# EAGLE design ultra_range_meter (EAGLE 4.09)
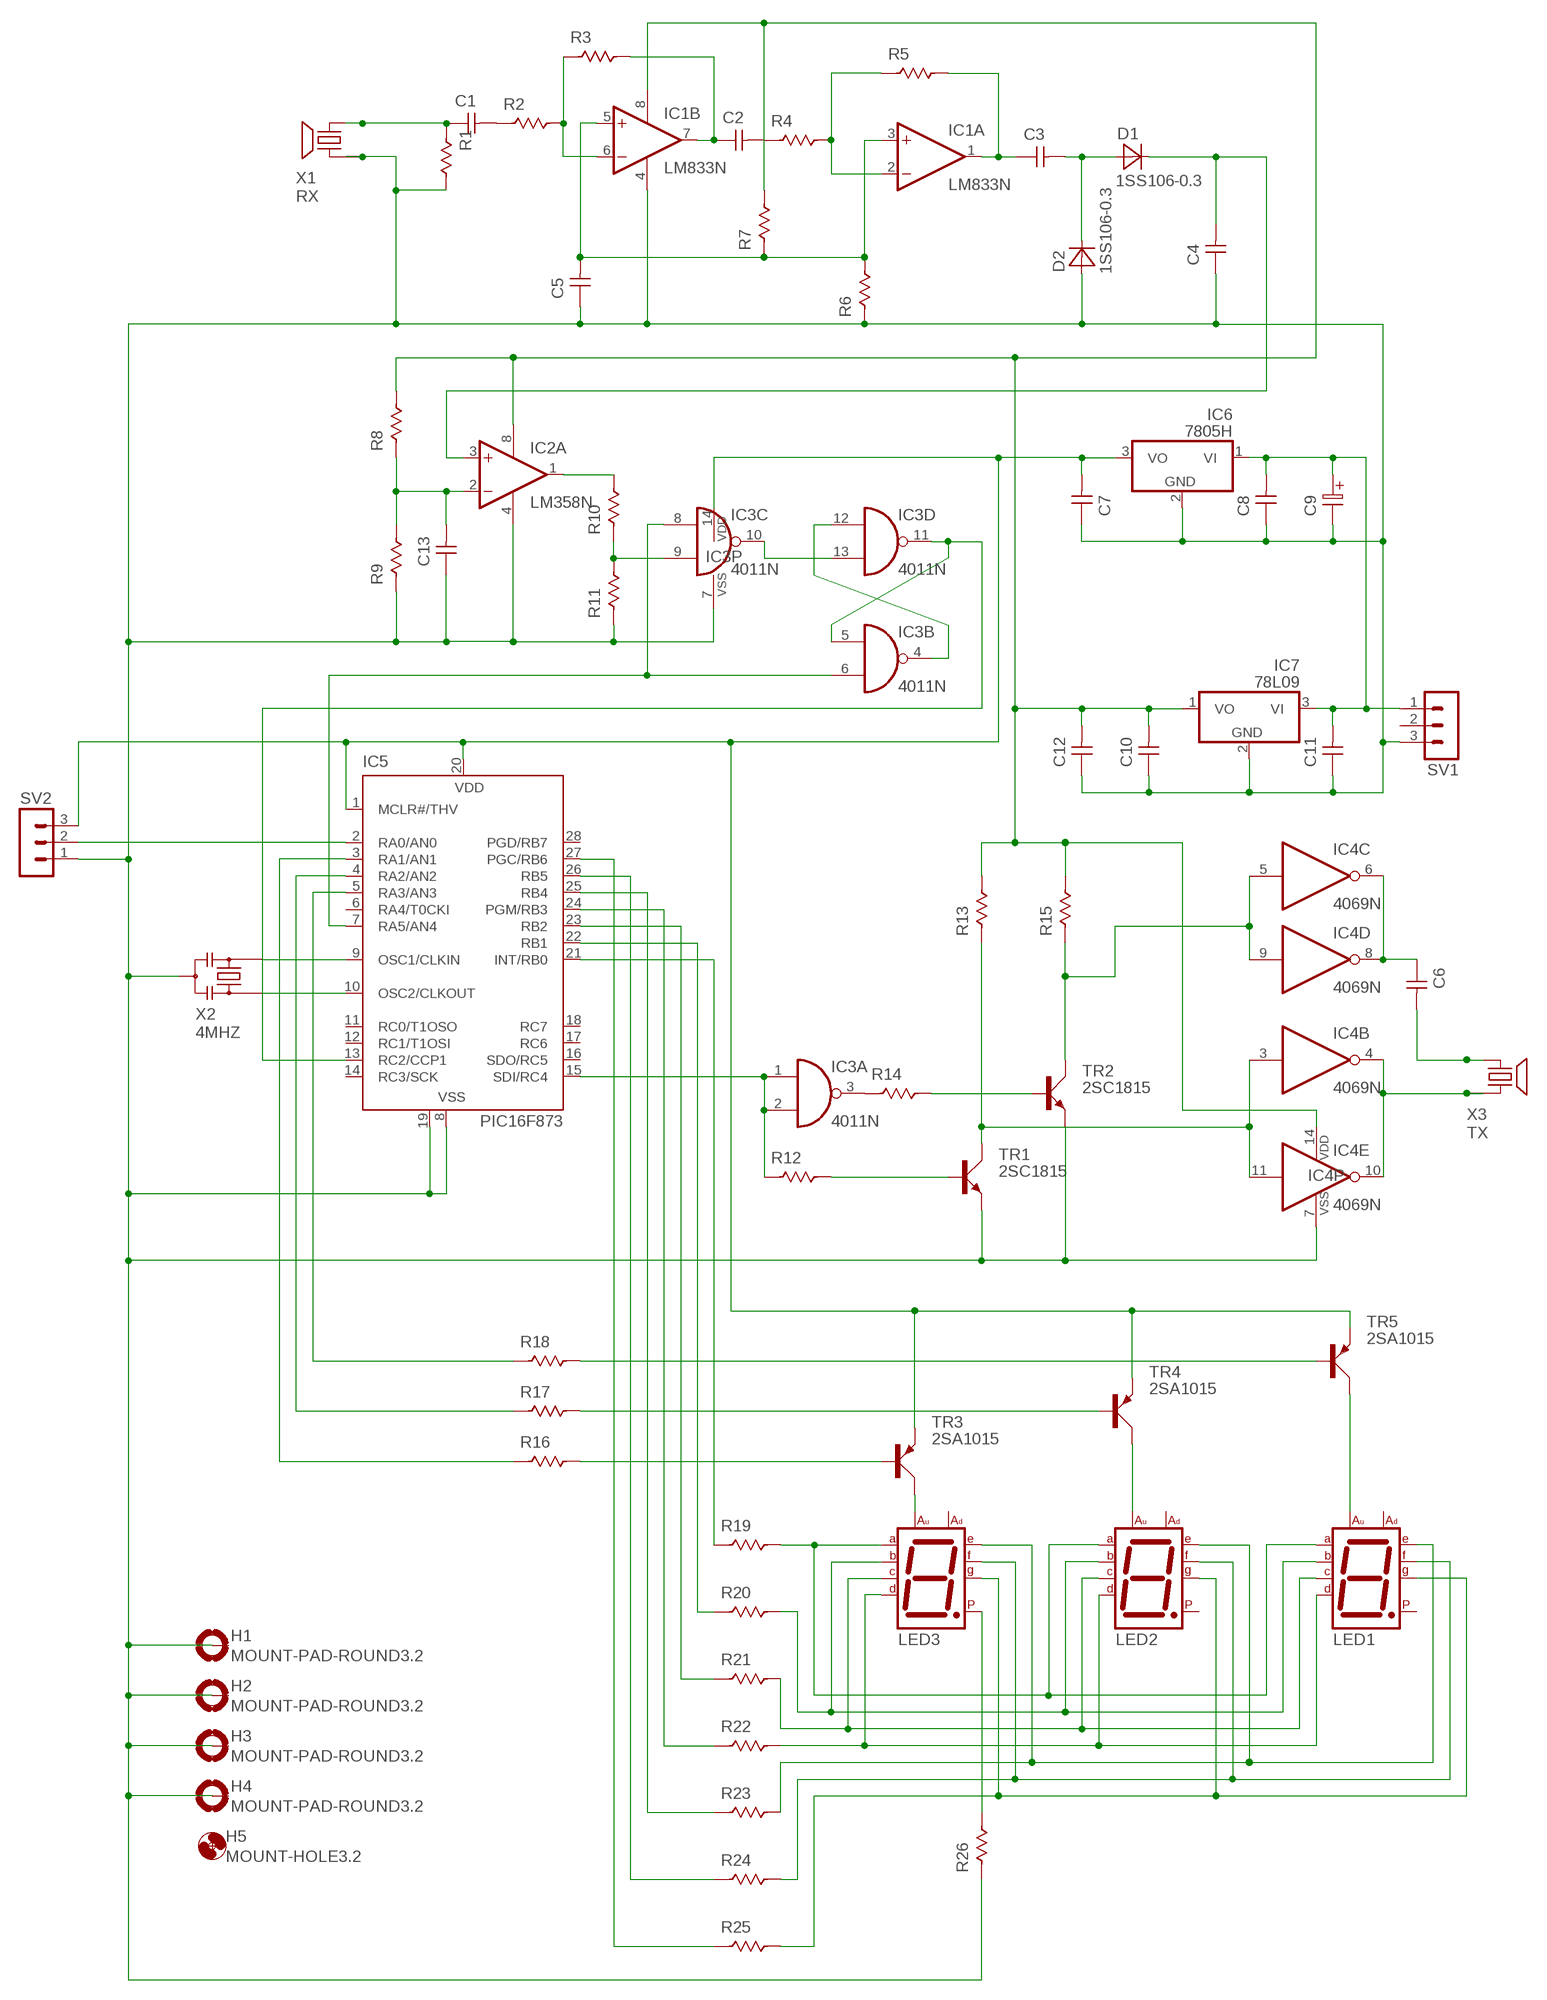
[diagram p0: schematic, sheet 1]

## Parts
C1  CAP-0.1  [C-0.1]
C2  CAP-0.1  [C-0.1]
C3  CAP-0.1  [C-0.1]
C4  CAP-0.1  [C-0.1]
C5  CAP-0.1  [C-0.1]
C6  CAP-0.1  [C-0.1]
C7  CAP-0.1  [C-0.1]
C8  CAP-0.1  [C-0.1]
C9  ELC-0.1X0.2  [E-0.1X0.2]
C10  CAP-0.1  [C-0.1]
C11  CAP-0.1  [C-0.1]
C12  CAP-0.1  [C-0.1]
C13  CAP-0.1  [C-0.1]
D1  1SS106-0.3  [D-0.3]
D2  1SS106-0.3  [D-0.3]
H1  MOUNT-PAD-ROUND3.2  [3,2-PAD]
H2  MOUNT-PAD-ROUND3.2  [3,2-PAD]
H3  MOUNT-PAD-ROUND3.2  [3,2-PAD]
H4  MOUNT-PAD-ROUND3.2  [3,2-PAD]
H5  MOUNT-HOLE3.2  [3,2]
IC1  LM833N  [DIL08]
IC2  LM358N  [DIL08]
IC3  4011N  [DIL14]
IC4  4069N  [DIL14]
IC5  PIC16F873  [DIL28-3]
IC6  7805H  [TO220H]
IC7  78L09  78L05  [TO92]
LED1  7SEG-A  [7SEG-13]
LED2  7SEG-A  [7SEG-13]
LED3  7SEG-A  [7SEG-13]
R1  RESI-0.3  [R-0.3]
R2  RESI-0.1  [R-0.1]
R3  RESI-0.1  [R-0.1]
R4  RESI-0.3  [R-0.3]
R5  RESI-0.1  [R-0.1]
R6  RESI-0.1  [R-0.1]
R7  RESI-0.1  [R-0.1]
R8  RESI-0.3  [R-0.3]
R9  RESI-0.3  [R-0.3]
R10  RESI-0.3  [R-0.3]
R11  RESI-0.3  [R-0.3]
R12  RESI-0.3  [R-0.3]
R13  RESI-0.3  [R-0.3]
R14  RESI-0.3  [R-0.3]
R15  RESI-0.3  [R-0.3]
R16  RESI-0.1  [R-0.1]
R17  RESI-0.1  [R-0.1]
R18  RESI-0.1  [R-0.1]
R19  RESI-0.3  [R-0.3]
R20  RESI-0.3  [R-0.3]
R21  RESI-0.3  [R-0.3]
R22  RESI-0.3  [R-0.3]
R23  RESI-0.3  [R-0.3]
R24  RESI-0.3  [R-0.3]
R25  RESI-0.3  [R-0.3]
R26  RESI-0.3  [R-0.3]
SV1  MA03-1  [MA03-1]
SV2  MA03-1  [MA03-1]
TR1  2SC1815  [TO92BCE]
TR2  2SC1815  [TO92BCE]
TR3  2SA1015  [TO92BCE]
TR4  2SA1015  [TO92BCE]
TR5  2SA1015  [TO92BCE]
X1  RX  [RX]
X2  4MHZ  [RESONATOR]
X3  TX  [TX]

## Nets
N$1: C1.1 R1.2 X1.1 X1.2
N$2: C1.2 R2.2
N$3: C2.2 R4.2
N$4: IC5.10(OSC2/CLKOUT) X2.3
N$5: IC5.9(OSC1/CLKIN) X2.1
N$6: IC5.21(INT/RB0) R19.2
N$7: IC5.22(RB1) R20.2
N$8: IC5.23(RB2) R21.2
N$9: IC5.24(PGM/RB3) R22.2
N$10: IC5.25(RB4) R23.2
N$11: IC5.26(RB5) R24.2
N$12: IC5.27(PGC/RB6) R25.2
N$13: IC3.1(A:I0) IC3.2(A:I1) IC5.15(SDI/RC4) R12.2
N$14: IC3.3(A:O) R14.2
N$15: IC5.2(RA0/AN0) SV2.2
N$16: IC5.5(RA3/AN3) R18.2
N$17: IC5.4(RA2/AN2) R17.2
N$18: IC5.3(RA1/AN1) R16.2
N$19: R16.1 TR3.B
N$20: R17.1 TR4.B
N$21: R18.1 TR5.B
N$22: R12.1 TR1.B
N$23: R14.1 TR2.B
N$24: LED1.4(C) LED2.4(C) LED3.4(C) R21.1
N$25: LED1.6(B) LED2.6(B) LED3.6(B) R20.1
N$26: IC4.3(B:I) IC4.11(E:I) R13.2 TR1.C
N$27 [power]: C8.2 C9.1 C11.2 IC6.1(VI) IC7.3(VI) SV1.1
N$28: C6.1 IC4.6(C:O) IC4.8(D:O)
N$29: LED1.1(E) LED2.1(E) LED3.1(E) R23.1
N$30: LED1.9(F) LED2.9(F) LED3.9(F) R24.1
N$31: C6.2 X3.1 X3.2
N$32: IC4.4(B:O) IC4.10(E:O) X3.3 X3.4
N$33: LED3.8(CA1) TR3.C
N$34: LED2.8(CA1) TR4.C
N$35: LED1.8(CA1) TR5.C
N$36: LED1.10(G) LED2.10(G) LED3.10(G) R25.1
N$37: IC1.2(A:-IN) R4.1 R5.2
N$38: C3.1 IC1.1(A:OUT) R5.1
N$39: C3.2 D1.A D2.K
N$40: C13.2 IC2.2(A:-IN) R8.2 R9.1
N$41 [power]: C7.2 IC3.14(P:VDD) IC5.1(MCLR#/THV) IC5.20(VDD) IC6.3(VO) SV2.3 TR3.E TR4.E TR5.E
N$42: IC2.1(A:OUT) R10.1
N$43: LED3.5(DP) R26.1
N$44: LED1.2(D) LED2.2(D) LED3.2(D) R22.1
N$45: IC3.9(C:I1) R10.2 R11.1
N$46: C4.2 D1.K IC2.3(A:+IN)
N$47: LED1.7(A) LED2.7(A) LED3.7(A) R19.1
N$48: IC3.5(B:I0) IC3.11(D:O) IC5.13(RC2/CCP1)
N$49: IC4.5(C:I) IC4.9(D:I) R15.2 TR2.C
N$50: IC3.4(B:O) IC3.12(D:I0)
N$51: IC3.10(C:O) IC3.13(D:I1)
N$52 [gnd]: C4.1 C5.1 C7.1 C8.1 C9.2 C10.1 C11.1 C12.1 C13.1 D2.A H1.B3,2(MOUNT) H2.B3,2(MOUNT) H3.B3,2(MOUNT) H4.B3,2(MOUNT) IC1.4(P:V-) IC2.4(P:V-) IC3.7(P:VSS) IC4.7(P:VSS) IC5.8(VSS) IC5.19(VSS) IC6.2(GND) IC7.2(GND) R1.1 R6.2 R9.2 R11.2 R26.2 SV1.3 SV2.1 TR1.E TR2.E X1.3 X1.4 X2.2
N$53: IC1.6(B:-IN) R2.1 R3.2
N$55: C2.1 IC1.7(B:OUT) R3.1
N$56: IC3.6(B:I1) IC3.8(C:I0) IC5.7(RA5/AN4)
N$57: C5.2 IC1.3(A:+IN) IC1.5(B:+IN) R6.1 R7.2
N$60 [power]: C10.2 C12.2 IC1.8(P:V+) IC2.8(P:V+) IC4.14(P:VDD) IC7.1(VO) R7.1 R8.1 R13.1 R15.1
Unconnected: IC2.5(B:+IN) IC2.6(B:-IN) IC2.7(B:OUT) IC4.1(A:I) IC4.2(A:O) IC4.12(F:O) IC4.13(F:I) IC5.6(RA4/T0CKI) IC5.11(RC0/T1OSO) IC5.12(RC1/T1OSI) IC5.14(RC3/SCK) IC5.16(SDO/RC5) IC5.17(RC6) IC5.18(RC7) IC5.28(PGD/RB7) LED1.3(CA2) LED1.5(DP) LED2.3(CA2) LED2.5(DP) LED3.3(CA2) SV1.2

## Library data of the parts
C1-C8 C10-C13 = 01_Capacitor:CAP-*: Non Pole Capacitor
C9 = 01_Capacitor:ELC-*: Electrolytic Capacitor
D1 D2 = 03_Diode:1SS106: Shottky barrier diode
H1-H4 = 92_Holes:MOUNT-PAD-ROUND: MOUNTING PAD, round
H5 = 92_Holes:MOUNT-HOLE: MOUNTING HOLE with drill center marker
IC1 = 10_Linear:LM833: OP AMP
IC2 = 10_Linear:LM358: OP AMP
IC3 = 07_40xx:4011: Quad 2-input NAND
IC4 = 07_40xx:4069: Hex INVERTER
IC5 = 11_PIC:PIC16F873: MICROCONTROLLER flash type
IC6 IC7 = 12_Regulator:78*: Positive Voltage Regulator
LED1-LED3 = 13_LED:7SEG-A: 7-segment LED Anode Common
R1-R26 = 02_Resistor:RESI-*: Resistor
SV1 SV2 = 91_Connector:MA03-1: PIN HEADER
TR1 TR2 = 05_Transistors:2SC*: NPN Transistor
TR3-TR5 = 05_Transistors:2SA*: PNP Transistor
X1 = 15_Sonar:RX: Receive Sonar
X2 = 14_Crystal:*MHZ: Resonator
X3 = 15_Sonar:TX: Transmit Sonar

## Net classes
1 gnd: width 0.914 mm, drill 0.254 mm
2 power: width 0.61 mm, drill 0.203 mm

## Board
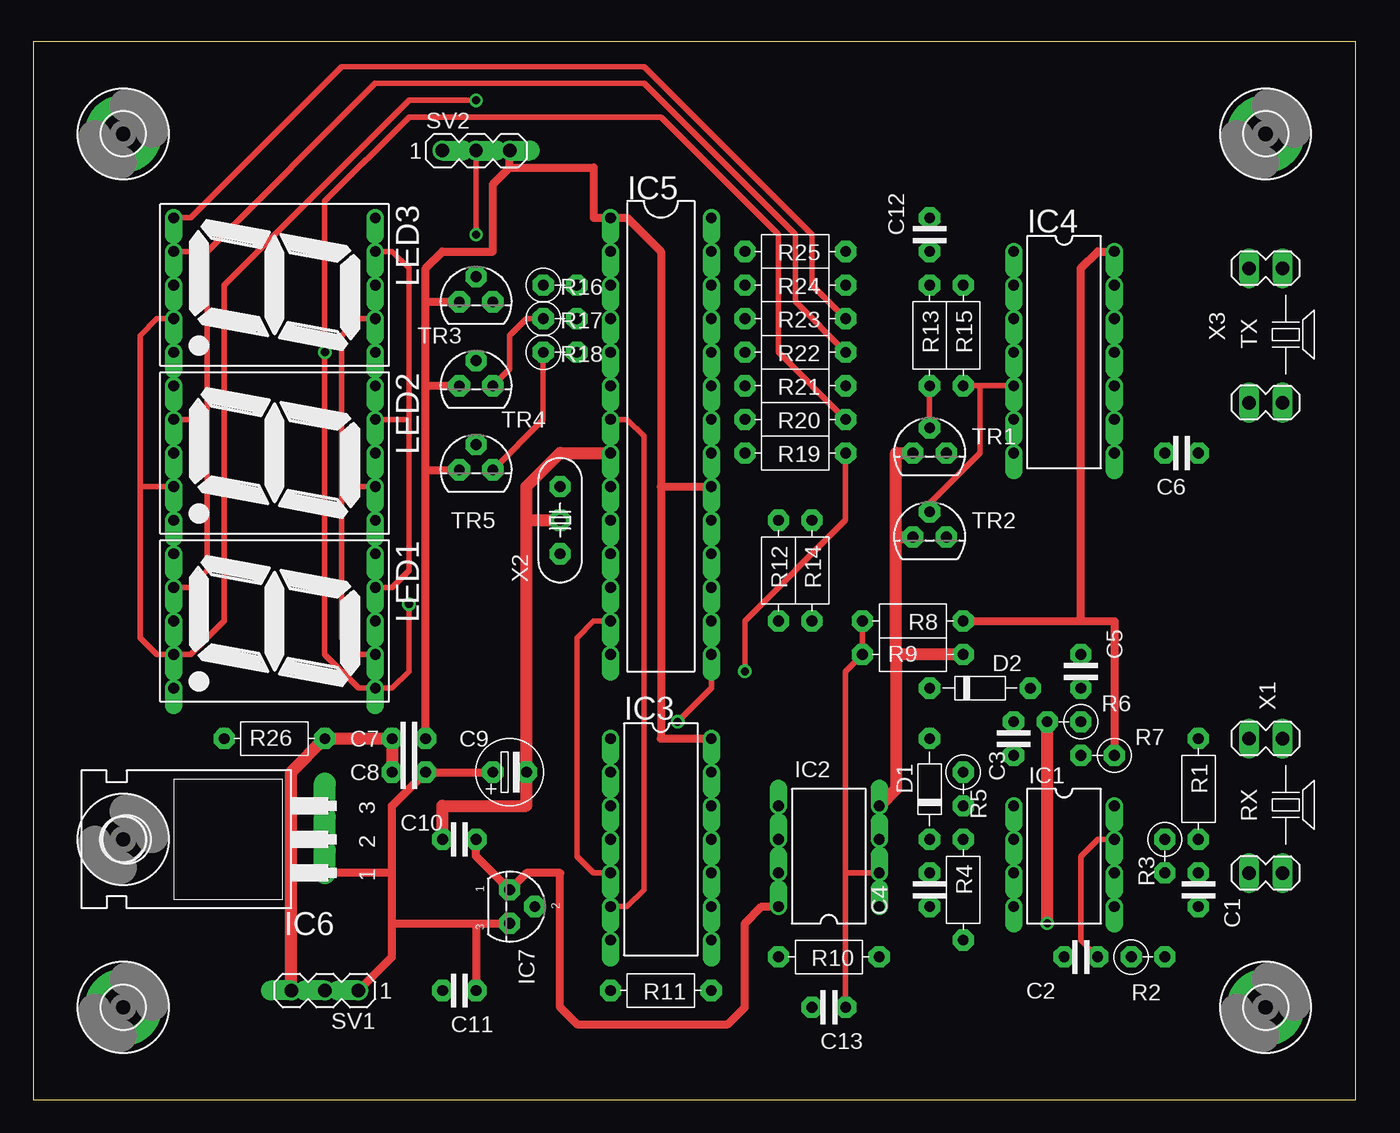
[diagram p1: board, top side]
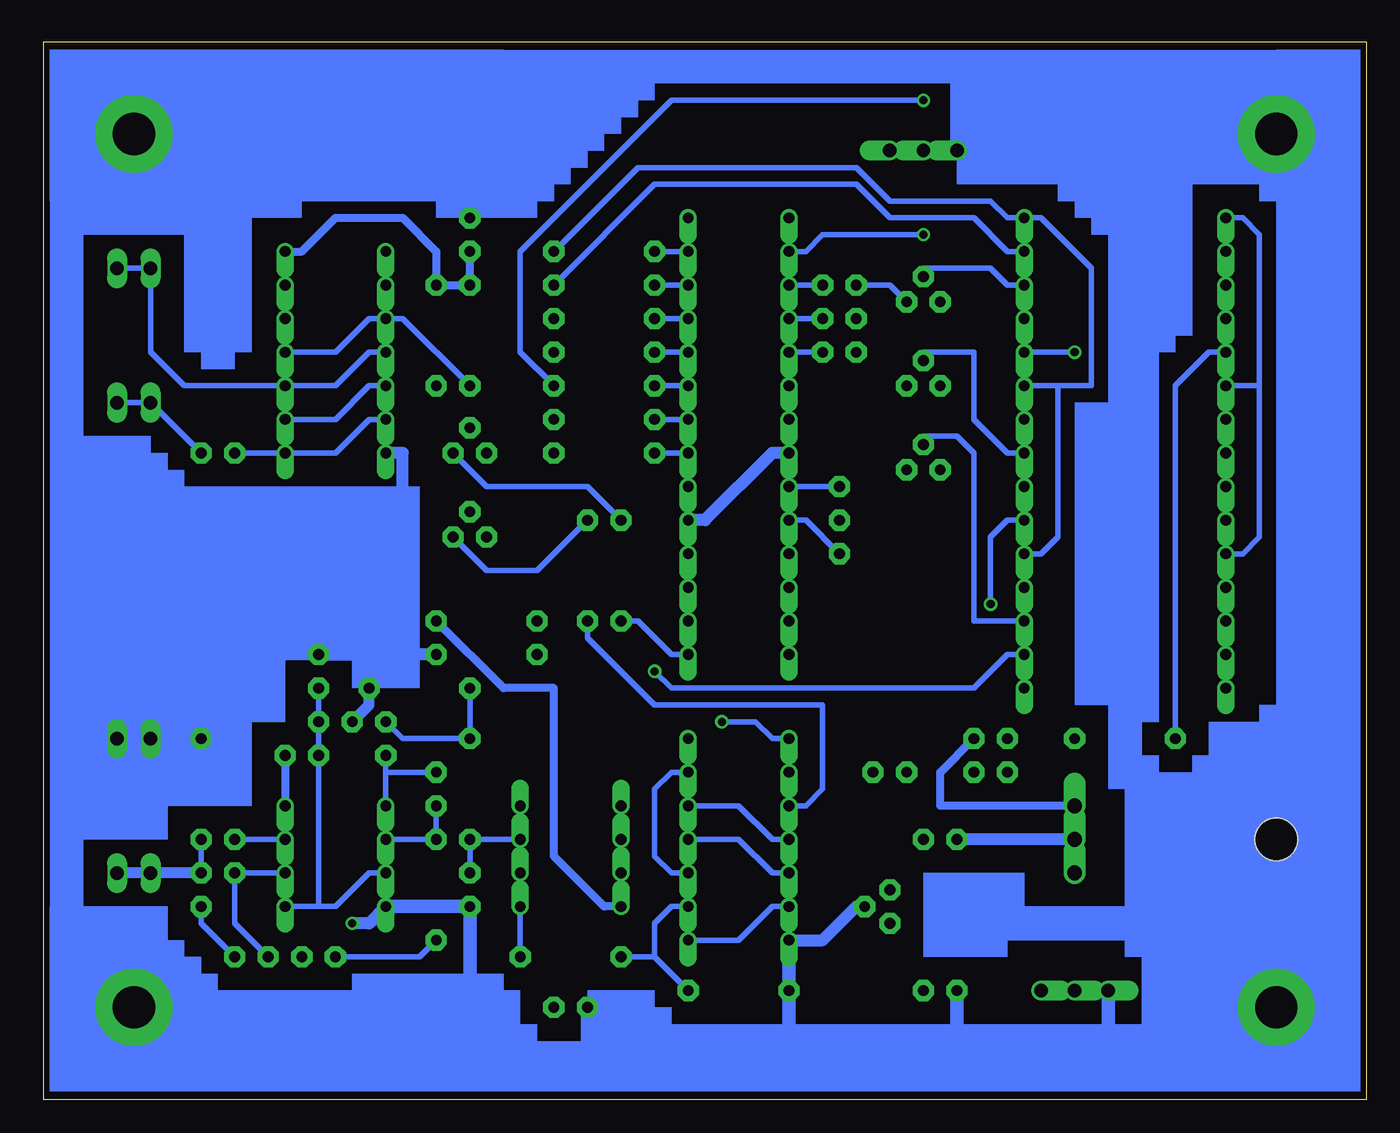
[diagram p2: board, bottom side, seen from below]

Size 100 x 80 mm. Coordinates in mm from the lower left corner, seen from the top.
Outline: 0,0 100,0 100,80 0,80 0,0
Copper layers used: Top, Bottom

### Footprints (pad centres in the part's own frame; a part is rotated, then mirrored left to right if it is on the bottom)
C-0.1 = drill 0.813 pad 1.6 octagon: 1 -1.27,0; 2 1.27,0
E-0.1X0.2 = drill 0.813 pad 1.6 octagon: 1 -1.27,0; 2 1.27,0
D-0.3 = drill 0.813 pad 1.6 octagon: A -3.81,0; K 3.81,0
3,2-PAD = drill 3.2 pad 5.842 round: B3,2 0,0
3,2 = hole 3.2: 0,0
DIL08 = drill 0.813 offset: 1 -3.81,-3.81; 2 -1.27,-3.81; 3 1.27,-3.81; 4 3.81,-3.81; 5 3.81,3.81; 6 1.27,3.81; 7 -1.27,3.81; 8 -3.81,3.81
DIL14 = drill 0.813 offset: 1 -7.62,-3.81; 2 -5.08,-3.81; 3 -2.54,-3.81; 4 0,-3.81; 5 2.54,-3.81; 6 5.08,-3.81; 7 7.62,-3.81; 8 7.62,3.81; 9 5.08,3.81; 10 2.54,3.81; 11 0,3.81; 12 -2.54,3.81; 13 -5.08,3.81; 14 -7.62,3.81
DIL28-3 = drill 0.813 offset: 1 -16.51,-3.81; 2 -13.97,-3.81; 3 -11.43,-3.81; 4 -8.89,-3.81; 5 -6.35,-3.81; 6 -3.81,-3.81; 7 -1.27,-3.81; 8 1.27,-3.81; 9 3.81,-3.81; 10 6.35,-3.81; 11 8.89,-3.81; 12 11.43,-3.81; 13 13.97,-3.81; 14 16.51,-3.81; 15 16.51,3.81; 16 13.97,3.81; 17 11.43,3.81; 18 8.89,3.81; 19 6.35,3.81; 20 3.81,3.81; 21 1.27,3.81; 22 -1.27,3.81; 23 -3.81,3.81; 24 -6.35,3.81; 25 -8.89,3.81; 26 -11.43,3.81; 27 -13.97,3.81; 28 -16.51,3.81
TO220H = drill 1.118 offset: 1 -2.54,-7.62; 2 0,-7.62; 3 2.54,-7.62
TO92 = drill 0.813 pad 1.6 octagon: 1 -1.27,0; 2 0,1.905; 3 1.27,0
7SEG-13 = drill 0.813 offset: 1 -5.08,-7.62; 2 -2.54,-7.62; 3 0,-7.62; 4 2.54,-7.62; 5 5.08,-7.62; 6 5.08,7.62; 7 2.54,7.62; 8 0,7.62; 9 -2.54,7.62; 10 -5.08,7.62
R-0.3 = drill 0.813 pad 1.6 octagon: 1 -3.81,0; 2 3.81,0
R-0.1 = drill 0.813 pad 1.6 octagon: 1 0,0; 2 2.54,0
MA03-1 = drill 1.016 offset: 1 -2.54,0; 2 0,0; 3 2.54,0
TO92BCE = drill 0.813 pad 1.6 octagon: B 1.27,-1.27; C 0,0.635; E -1.27,-1.27
RX = drill 1.016 long: 1 5.08,1.27; 2 5.08,-1.27; 3 -5.08,1.27; 4 -5.08,-1.27
RESONATOR = drill 0.813 pad 1.6 octagon: 1 -2.54,0; 2 0,0; 3 2.54,0
TX = drill 1.016 long: 1 5.08,1.27; 2 5.08,-1.27; 3 -5.08,1.27; 4 -5.08,-1.27

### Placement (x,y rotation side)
C1  88.1,15.87 270 top
C2  79.21,10.79 180 top
C3  74.13,27.3 90 top
C4  67.78,15.87 90 top
C5  79.21,32.38 270 top
C6  86.83,48.89 0 top
C7  28.41,27.3 0 top
C8  28.41,24.76 0 top
C9  36.03,24.76 0 top
C10  32.22,19.68 0 top
C11  32.22,8.25 0 top
C12  67.78,65.4 270 top
C13  60.16,6.98 0 top
D1  67.78,23.49 270 top
D2  71.59,31.11 180 top
H1  6.82,73.02 0 top
H2  6.82,6.98 0 top
H3  93.18,6.98 0 top
H4  93.18,73.02 0 top
H5  6.82,19.68 0 top
IC1  77.94,18.41 270 top
IC2  60.16,18.41 90 top
IC3  47.46,19.68 270 top
IC4  77.94,56.51 270 top
IC5  47.46,50.16 270 top
IC6  14.44,19.68 90 top
IC7  36.03,14.6 270 top
LED1  18.25,36.19 270 top
LED2  18.25,48.89 270 top
LED3  18.25,61.59 270 top
R1  88.1,23.49 270 top
R2  83.02,10.79 0 top
R3  85.56,19.68 270 top
R4  70.32,15.87 270 top
R5  70.32,24.76 270 top
R6  79.21,28.57 180 top
R7  81.75,26.03 180 top
R8  66.51,36.19 180 top
R9  66.51,33.65 0 top
R10  60.16,10.79 180 top
R11  47.46,8.25 180 top
R12  56.35,40 270 top
R13  67.78,57.78 270 top
R14  58.89,40 270 top
R15  70.32,57.78 270 top
R16  38.57,61.59 0 top
R17  38.57,59.05 0 top
R18  38.57,56.51 0 top
R19  57.62,48.89 180 top
R20  57.62,51.43 180 top
R21  57.62,53.97 180 top
R22  57.62,56.51 180 top
R23  57.62,59.05 180 top
R24  57.62,61.59 180 top
R25  57.62,64.13 180 top
R26  18.25,27.3 0 top
SV1  22.06,8.25 180 top
SV2  33.49,71.75 0 top
TR1  67.78,50.16 0 top
TR2  67.78,43.81 0 top
TR3  33.49,61.59 0 top
TR4  33.49,55.24 0 top
TR5  33.49,48.89 0 top
X1  93.18,22.22 270 top
X2  39.84,43.81 270 top
X3  93.18,57.78 270 top

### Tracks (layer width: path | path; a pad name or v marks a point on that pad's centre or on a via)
N$1
  Bottom 0.406: C1.1 R1.2
  Bottom 0.813: C1.1 X1.2 X1.1
N$2
  Bottom 0.406: R2.2 88.1,13.33 C1.2
N$3
  Bottom 0.406: R4.2 71.59,10.79 C2.2
N$4
  Bottom 0.406: X2.3 42.38,43.81 IC5.10
N$5
  Bottom 0.406: X2.1 IC5.9
N$6
  Bottom 0.406: IC5.21 R19.2
N$7
  Bottom 0.406: IC5.22 R20.2
N$8
  Bottom 0.406: IC5.23 R21.2
N$9
  Bottom 0.406: IC5.24 R22.2
N$10
  Bottom 0.406: IC5.25 R23.2
N$11
  Bottom 0.406: IC5.26 R24.2
N$12
  Bottom 0.406: IC5.27 R25.2
N$13  (via drill 0.61)
  Top 0.406: v48.73,28.57 51.27,31.11 IC5.15
  Bottom 0.406: R12.2 55.08,36.19 52.54,33.65 IC5.15 | v48.73,28.57 46.19,28.57 44.92,27.3 IC3.1 IC3.2
N$14
  Bottom 0.406: R14.2 58.89,34.92 53.81,29.84 41.11,29.84 41.11,23.49 42.38,22.22 IC3.3
N$15  (via drill 0.61)
  Top 0.406: v33.49,65.4 SV2.2
  Bottom 0.406: v33.49,65.4 41.11,65.4 42.38,64.13 IC5.2
N$16
  Bottom 0.406: R18.2 IC5.5
N$17
  Bottom 0.406: R17.2 IC5.4
N$18
  Bottom 0.406: R16.2 IC5.3
N$19
  Bottom 0.406: TR3.B 36.03,61.59 R16.1
N$20
  Top 0.406: TR4.B 36.03,55.24 36.03,57.78 37.3,59.05 R17.1
N$21
  Top 0.406: TR5.B 38.57,51.43 R18.1
N$22
  Bottom 0.406: R12.1 58.89,46.35 66.51,46.35 TR1.B
N$23
  Bottom 0.406: R14.1 62.7,40 66.51,40 TR2.B
N$24  (via drill 0.61)
  Top 0.406: 8.09,46.35 8.09,34.92 9.36,33.65 LED1.4 11.9,33.65 14.44,36.19 14.44,61.59 28.41,75.56 v33.49,75.56 | 8.09,46.35 LED2.4 | 8.09,46.35 8.09,57.78 9.36,59.05 LED3.4
  Bottom 0.406: R21.1 63.97,56.51 63.97,64.13 52.54,75.56 v33.49,75.56
N$25  (via drill 0.61)
  Top 0.406: v28.41,37.46 28.41,32.38 27.14,31.11 LED1.6 24.6,31.11 22.06,33.65 v22.06,56.51 22.06,67.94 28.41,74.29 47.46,74.29 56.35,65.4 56.35,56.51 R20.1
  Bottom 0.406: v28.41,37.46 28.41,42.54 27.14,43.81 LED2.6 | v22.06,56.51 LED3.6
N$26
  Top 0.406: TR1.C R13.2
  Bottom 0.406: R13.2 72.86,59.05 IC4.3 75.4,59.05 77.94,56.51 IC4.11
N$27
  Top 0.61: 33.49,13.33 IC7.3 | C9.1 C8.2 27.14,22.22 27.14,13.33 | 27.14,13.33 27.14,17.14 IC6.1 | SV1.1 27.14,10.79 27.14,13.33 | 27.14,13.33 33.49,13.33 | 33.49,13.33 C11.2
N$28
  Bottom 0.406: IC4.6 75.4,51.43 77.94,48.89 IC4.8 C6.1
N$29
  Top 0.406: R23.1 58.89,61.59 58.89,65.4 46.19,78.1 23.33,78.1 11.9,66.67 LED3.1
  Bottom 0.406: 8.09,53.97 8.09,42.54 9.36,41.27 LED1.1 | 8.09,53.97 LED2.1 | 8.09,53.97 8.09,65.4 9.36,66.67 LED3.1
N$30
  Top 0.406: 28.41,51.43 28.41,40 27.14,38.73 LED1.9 | 28.41,51.43 LED2.9 | 28.41,51.43 28.41,62.86 27.14,64.13 LED3.9
  Bottom 0.406: R24.1 53.81,69.21 38.57,69.21 36.03,66.67 29.68,66.67 27.14,64.13 LED3.9
N$31
  Bottom 0.406: C6.2 X3.2 X3.1
N$32
  Bottom 0.406: IC4.4 75.4,56.51 77.94,53.97 IC4.10 89.37,53.97 91.91,56.51 X3.4 X3.3
N$33
  Bottom 0.406: LED3.8 27.14,61.59 28.41,62.86 33.49,62.86 TR3.C
N$34
  Bottom 0.406: LED2.8 27.14,48.89 29.68,51.43 29.68,56.51 33.49,56.51 TR4.C
N$35
  Bottom 0.406: LED1.8 29.68,36.19 29.68,48.89 30.95,50.16 33.49,50.16 TR5.C
N$36
  Bottom 0.406: 23.33,53.97 23.33,42.54 24.6,41.27 LED1.10 | 23.33,53.97 LED2.10 | 23.33,53.97 20.79,53.97 20.79,62.86 24.6,66.67 LED3.10 27.14,66.67 28.41,67.94 36.03,67.94 38.57,70.48 55.08,70.48 R25.1
N$37
  Bottom 0.406: IC1.2 R4.1 R5.2
N$38
  Bottom 0.406: 74.13,24.76 IC1.1 | 74.13,24.76 C3.1 | R5.1 74.13,24.76
N$39
  Bottom 0.406: C3.2 72.86,27.3 D1.A D2.K
N$40
  Top 0.406: R8.2 R9.1 61.43,32.38 61.43,17.14 | C13.2 61.43,17.14 | 61.43,17.14 IC2.2
N$41
  Top 0.61: 47.46,46.35 47.46,27.3 IC3.14 | 47.46,46.35 47.46,64.13 44.92,66.67 IC5.1 42.38,66.67 42.38,70.48 36.03,70.48 | 47.46,46.35 IC5.20 | 29.68,47.62 TR5.E | C7.2 29.68,47.62 | 29.68,53.97 TR4.E | 29.68,47.62 29.68,53.97 | 29.68,60.32 TR3.E | 29.68,53.97 29.68,60.32 | 36.03,70.48 34.76,69.21 34.76,64.13 30.95,64.13 29.68,62.86 29.68,60.32 | 36.03,70.48 SV2.3
  Bottom 0.61: C7.2 32.22,24.76 32.22,22.22 IC6.3
N$42
  Bottom 0.406: R10.1 IC2.1
N$43
  Bottom 0.406: R26.1 14.44,53.97 11.9,56.51 LED3.5
N$44
  Top 0.406: 13.17,51.43 13.17,40 11.9,38.73 LED1.2 | 13.17,51.43 LED2.2 | 13.17,51.43 13.17,64.13 | 13.17,64.13 LED3.2 | R22.1 57.62,60.32 57.62,65.4 46.19,76.83 25.87,76.83 13.17,64.13
N$45
  Bottom 0.406: R11.1 53.81,10.79 | 53.81,10.79 53.81,13.33 52.54,14.6 IC3.9 | 53.81,10.79 R10.2
N$46
  Bottom 0.406: C4.2 D1.K IC2.3
N$47  (via drill 0.61)
  Top 0.406: 23.33,46.35 23.33,34.92 24.6,33.65 LED1.7 | 23.33,46.35 LED2.7 | 23.33,46.35 23.33,57.78 24.6,59.05 LED3.7 | R19.1 61.43,43.81 53.81,36.19 v53.81,32.38
  Bottom 0.406: v53.81,32.38 52.54,31.11 29.68,31.11 27.14,33.65 LED1.7
N$48
  Top 0.406: IC5.13 42.38,36.19 41.11,34.92 41.11,18.41 42.38,17.14 IC3.5
  Bottom 0.406: IC3.5 44.92,17.14 47.46,19.68 IC3.11
N$49
  Top 0.406: 71.59,53.97 71.59,48.89 67.78,45.08 TR2.C | 71.59,53.97 R15.2 | 71.59,53.97 IC4.5
  Bottom 0.406: IC4.9 77.94,51.43 75.4,53.97 IC4.5
N$50
  Bottom 0.406: IC3.4 44.92,19.68 47.46,22.22 IC3.12
N$51
  Bottom 0.406: IC3.10 52.54,17.14 53.81,18.41 53.81,23.49 52.54,24.76 IC3.13
N$52  (via drill 0.61)
  Top 0.914: C8.1 C7.1 R26.2 19.52,24.76 19.52,19.68 | 37.3,43.81 C9.2 37.3,22.22 30.95,22.22 C10.1 | 19.52,19.68 IC6.2 | SV1.3 19.52,19.68 | 37.3,43.81 X2.2 | 37.3,43.81 37.3,46.35 39.84,48.89 IC5.8 | R9.2 65.24,33.65 | 65.24,42.54 TR2.E | 65.24,33.65 65.24,42.54 | 65.24,33.65 65.24,23.49 IC2.4 | TR1.E 65.24,48.89 65.24,42.54 | v76.67,13.33 R6.2
  Bottom 0.813: R6.2 75.4,29.84 D2.A | 75.4,33.65 R9.2 | C5.1 88.1,33.65 R1.1 X1.4 X1.3 98.26,27.3
  Bottom 0.914: IC5.8 44.92,48.89 50,43.81 IC5.19 | D2.A 75.4,33.65 C5.1 81.75,33.65 | R9.2 72.86,33.65 72.86,48.89 IC4.7 | IC7.2 38.57,14.6 41.11,12.06 IC3.7 | IC6.2 C10.1 | IC1.4 75.4,13.33 v76.67,13.33
  Bottom 1.016: 19.52,3.17 SV1.3 | IC3.7 R11.2 43.65,3.17 | 30.95,3.17 C11.1 | 58.89,3.17 C13.1 | 67.78,3.17 C4.1 IC1.4 | 30.95,78.1 SV2.1 | 67.78,78.1 C12.1
  Bottom 2.54: H2.B3,2 6.82,3.17 19.52,3.17 30.95,3.17 43.65,3.17 58.89,3.17 67.78,3.17 93.18,3.17 H3.B3,2 98.26,6.98 98.26,27.3 98.26,73.02 H4.B3,2 93.18,78.1 67.78,78.1 30.95,78.1 6.82,78.1 H1.B3,2 3.01,73.02 3.01,6.98 H2.B3,2
N$53
  Bottom 0.406: IC1.6 R3.2 85.56,13.33 R2.1
N$55
  Top 0.406: C2.1 79.21,12.06 79.21,18.41 80.48,19.68 IC1.7
  Bottom 0.406: IC1.7 R3.1
N$56
  Top 0.406: IC5.7 44.92,51.43 46.19,50.16 46.19,15.87 44.92,14.6 IC3.6
  Bottom 0.406: IC3.6 44.92,14.6 47.46,12.06 IC3.8
N$57
  Bottom 0.406: 79.21,14.6 77.94,14.6 75.4,17.14 IC1.3 | 79.21,14.6 IC1.5 | 79.21,14.6 R7.2 R6.1 C5.2
N$60
  Top 0.61: 79.21,36.19 81.75,36.19 R7.1 | R8.1 79.21,36.19 | 79.21,36.19 79.21,62.86 80.48,64.13 IC4.14 | C10.2 33.49,18.41 IC7.1 37.3,17.14 39.84,17.14 39.84,6.98 41.11,5.71 52.54,5.71 53.81,6.98 53.81,13.33 55.08,14.6 IC2.8
  Bottom 0.61: IC4.14 80.48,64.13 77.94,66.67 72.86,66.67 70.32,64.13 R15.1 R13.1 C12.2 | R8.1 65.24,31.11 61.43,31.11 61.43,18.41 57.62,14.6 IC2.8 | R7.1 IC1.8
(copper drawn outside any net)
  shapes: Bottom area x54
